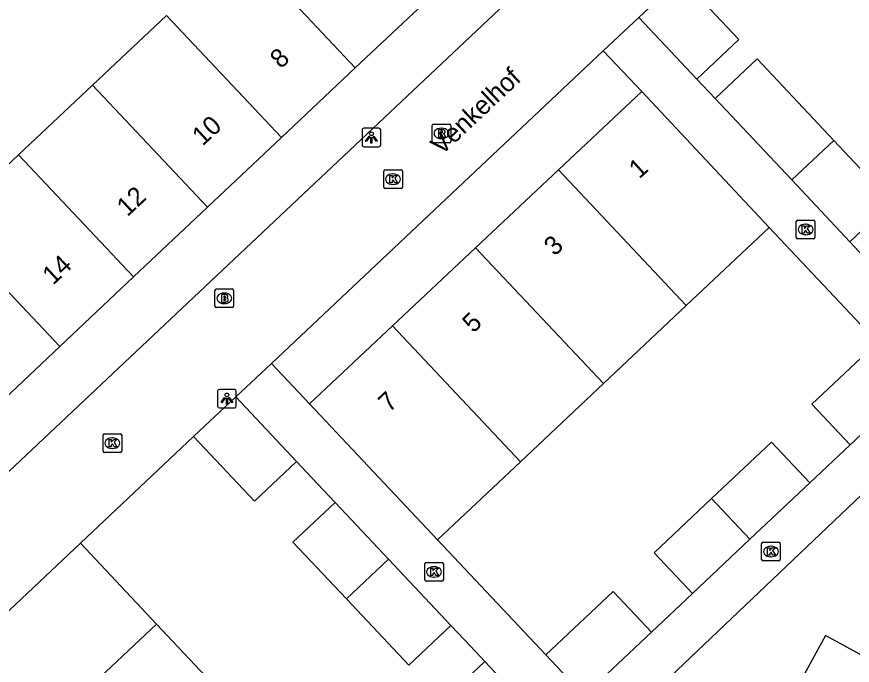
# Model space of a CAD drawing. Extents: x 162542 to 163144, y 380786 to 381511.
# Drawn here: x 162912.05 to 162956.88, y 381257.93 to 381292.72 of the extents above; entities that cross this region are included whole.
import ezdxf

# ---------------------------------------------------------------- set-up
doc = ezdxf.new("R2010")
doc.units = 0
for name, color, linetype in [('IMGEO_Brandkraan', 7, 'Continuous'), ('IMGEO_Kolk', 7, 'Continuous'), ('IMGEO_Lichtpunt', 7, 'Continuous'), ('IMGEO_Muur', 7, 'Continuous'), ('IMGEO_Openbare_ruimte_label', 7, 'Continuous'), ('IMGEO_Pand', 7, 'Continuous'), ('IMGEO_Pand_nummerreeks', 7, 'Continuous'), ('IMGEO_Rijbaan_lokaal_open', 7, 'Continuous'), ('IMGEO_Rioolput', 7, 'Continuous'), ('IMGEO_Voetpad_open', 7, 'Continuous')]:
    doc.layers.add(name, color=color, linetype=linetype)

msp = doc.modelspace()

# ---------------------------------------------------------------- linework, layer by layer
at = {"layer": 'IMGEO_Brandkraan'}
for p, q in [((162922.686, 381277.188), (162922.686, 381278.04)), ((162922.761, 381278.114), (162923.613, 381278.114)), ((162923.174, 381277.894), (162923.199, 381277.894)), ((162923.687, 381278.04), (162923.687, 381277.188)), ((162923.197, 381277.334), (162923.172, 381277.334)), ((162923.613, 381277.114), (162922.761, 381277.114))]:
    msp.add_line(p, q, dxfattribs=at)
for points in [[(162922.686, 381277.188), (162922.686, 381278.04)], [(162922.761, 381278.114), (162923.613, 381278.114)], [(162923.034, 381277.814), (162923.034, 381277.414), (162923.247, 381277.414)], [(162923.265, 381277.814), (162923.034, 381277.814)], [(162923.213, 381277.733), (162923.159, 381277.733), (162923.159, 381277.657)], [(162923.687, 381278.04), (162923.687, 381277.188)], [(162923.159, 381277.657), (162923.212, 381277.657)], [(162923.221, 381277.581), (162923.159, 381277.581), (162923.159, 381277.5)], [(162923.159, 381277.5), (162923.221, 381277.5)], [(162923.613, 381277.114), (162922.761, 381277.114)]]:
    msp.add_lwpolyline(points, dxfattribs=at)
for centre, radius, start, end in [((162922.763, 381278.038), 0.0765, 91.552, 178.448), ((162922.763, 381278.038), 0.0765, 91.552, 178.448), ((162923.214, 381277.695), 0.0379, 267.8285, 90.9355), ((162923.269, 381277.669), 0.145, 59.4692, 91.5367), ((162923.294, 381277.716), 0.0922, 285.5137, 58.1501), ((162923.611, 381278.038), 0.0765, 1.552, 88.448), ((162923.611, 381278.038), 0.0765, 1.552, 88.448), ((162923.222, 381277.54), 0.0404, 269.8759, 90.5077), ((162923.253, 381277.665), 0.251, 268.6676, 293.5347), ((162923.299, 381277.524), 0.105, 301.3115, 78.989), ((162922.763, 381277.19), 0.0765, 181.552, 268.448), ((162922.763, 381277.19), 0.0765, 181.552, 268.448), ((162923.611, 381277.19), 0.0765, 271.552, 358.448), ((162923.611, 381277.19), 0.0765, 271.552, 358.448)]:
    msp.add_arc(centre, radius, start, end, dxfattribs=at)
for centre, major_axis, ratio, start_param, end_param in [((162923.173, 381277.614), (-0.387, 0.002), 0.722429, 4.712389, 7.853982), ((162923.198, 381277.614), (-0.39, 0.002), 0.717154, 1.570796, 4.712389)]:
    msp.add_ellipse(centre, major_axis=major_axis, ratio=ratio, start_param=start_param, end_param=end_param, dxfattribs=at)
at = {"layer": 'IMGEO_Kolk'}
for p, q in [((162931.742, 381283.579), (162931.742, 381284.431)), ((162931.817, 381284.505), (162932.669, 381284.505)), ((162932.743, 381284.431), (162932.743, 381283.579)), ((162932.23, 381284.285), (162932.255, 381284.285)), ((162932.253, 381283.725), (162932.228, 381283.725)), ((162932.669, 381283.505), (162931.817, 381283.505)), ((162953.871, 381280.88), (162953.871, 381281.732)), ((162953.946, 381281.806), (162954.798, 381281.806)), ((162954.872, 381281.732), (162954.872, 381280.88)), ((162954.359, 381281.586), (162954.384, 381281.586)), ((162954.382, 381281.026), (162954.357, 381281.026)), ((162954.798, 381280.806), (162953.946, 381280.806)), ((162916.684, 381269.416), (162916.684, 381270.268)), ((162916.759, 381270.342), (162917.611, 381270.342)), ((162917.172, 381270.122), (162917.197, 381270.122)), ((162917.685, 381270.268), (162917.685, 381269.416)), ((162917.611, 381269.342), (162916.759, 381269.342)), ((162917.195, 381269.562), (162917.17, 381269.562)), ((162952.01, 381263.603), (162952.01, 381264.455)), ((162952.085, 381264.529), (162952.937, 381264.529)), ((162952.498, 381264.309), (162952.523, 381264.309)), ((162953.011, 381264.455), (162953.011, 381263.603)), ((162933.939, 381262.512), (162933.939, 381263.364)), ((162934.014, 381263.438), (162934.866, 381263.438)), ((162934.94, 381263.364), (162934.94, 381262.512)), ((162952.937, 381263.529), (162952.085, 381263.529)), ((162952.521, 381263.749), (162952.496, 381263.749)), ((162934.427, 381263.218), (162934.452, 381263.218)), ((162934.45, 381262.658), (162934.425, 381262.658)), ((162934.866, 381262.438), (162934.014, 381262.438))]:
    msp.add_line(p, q, dxfattribs=at)
for points in [[(162931.742, 381283.579), (162931.742, 381284.431)], [(162931.817, 381284.505), (162932.669, 381284.505)], [(162932.743, 381284.431), (162932.743, 381283.579)], [(162932.063, 381284.205), (162932.186, 381284.205), (162932.186, 381284.054), (162932.316, 381284.205), (162932.48, 381284.205), (162932.334, 381284.054), (162932.487, 381283.805), (162932.335, 381283.805), (162932.25, 381283.969), (162932.186, 381283.902), (162932.186, 381283.805), (162932.063, 381283.805), (162932.063, 381284.205)], [(162932.669, 381283.505), (162931.817, 381283.505)], [(162953.871, 381280.88), (162953.871, 381281.732)], [(162953.946, 381281.806), (162954.798, 381281.806)], [(162954.872, 381281.732), (162954.872, 381280.88)], [(162954.192, 381281.506), (162954.315, 381281.506), (162954.315, 381281.355), (162954.445, 381281.506), (162954.609, 381281.506), (162954.463, 381281.355), (162954.616, 381281.106), (162954.464, 381281.106), (162954.379, 381281.27), (162954.315, 381281.203), (162954.315, 381281.106), (162954.192, 381281.106), (162954.192, 381281.506)], [(162954.798, 381280.806), (162953.946, 381280.806)], [(162916.684, 381269.416), (162916.684, 381270.268)], [(162916.759, 381270.342), (162917.611, 381270.342)], [(162917.685, 381270.268), (162917.685, 381269.416)], [(162917.005, 381270.042), (162917.128, 381270.042), (162917.128, 381269.891), (162917.258, 381270.042), (162917.422, 381270.042), (162917.276, 381269.891), (162917.429, 381269.642), (162917.277, 381269.642), (162917.192, 381269.806), (162917.128, 381269.739), (162917.128, 381269.642), (162917.005, 381269.642), (162917.005, 381270.042)], [(162917.611, 381269.342), (162916.759, 381269.342)], [(162952.01, 381263.603), (162952.01, 381264.455)], [(162952.085, 381264.529), (162952.937, 381264.529)], [(162953.011, 381264.455), (162953.011, 381263.603)], [(162952.331, 381264.229), (162952.454, 381264.229), (162952.454, 381264.078), (162952.584, 381264.229), (162952.748, 381264.229), (162952.602, 381264.078), (162952.755, 381263.829), (162952.603, 381263.829), (162952.518, 381263.993), (162952.454, 381263.926), (162952.454, 381263.829), (162952.331, 381263.829), (162952.331, 381264.229)], [(162933.939, 381262.512), (162933.939, 381263.364)], [(162934.014, 381263.438), (162934.866, 381263.438)], [(162934.94, 381263.364), (162934.94, 381262.512)], [(162952.937, 381263.529), (162952.085, 381263.529)], [(162934.26, 381263.138), (162934.383, 381263.138), (162934.383, 381262.987), (162934.513, 381263.138), (162934.677, 381263.138), (162934.531, 381262.987), (162934.684, 381262.738), (162934.532, 381262.738), (162934.447, 381262.902), (162934.383, 381262.835), (162934.383, 381262.738), (162934.26, 381262.738), (162934.26, 381263.138)], [(162934.866, 381262.438), (162934.014, 381262.438)]]:
    msp.add_lwpolyline(points, dxfattribs=at)
for centre, start, end in [((162931.819, 381284.429), 91.552, 178.448), ((162931.819, 381284.429), 91.552, 178.448), ((162932.667, 381284.429), 1.552, 88.448), ((162932.667, 381284.429), 1.552, 88.448), ((162931.819, 381283.581), 181.552, 268.448), ((162931.819, 381283.581), 181.552, 268.448), ((162932.667, 381283.581), 271.552, 358.448), ((162932.667, 381283.581), 271.552, 358.448), ((162953.948, 381281.73), 91.552, 178.448), ((162953.948, 381281.73), 91.552, 178.448), ((162954.796, 381281.73), 1.552, 88.448), ((162954.796, 381281.73), 1.552, 88.448), ((162953.948, 381280.882), 181.552, 268.448), ((162953.948, 381280.882), 181.552, 268.448), ((162954.796, 381280.882), 271.552, 358.448), ((162954.796, 381280.882), 271.552, 358.448), ((162916.761, 381270.266), 91.552, 178.448), ((162916.761, 381270.266), 91.552, 178.448), ((162917.609, 381270.266), 1.552, 88.448), ((162917.609, 381270.266), 1.552, 88.448), ((162916.761, 381269.418), 181.552, 268.448), ((162916.761, 381269.418), 181.552, 268.448), ((162917.609, 381269.418), 271.552, 358.448), ((162917.609, 381269.418), 271.552, 358.448), ((162952.087, 381264.453), 91.552, 178.448), ((162952.087, 381264.453), 91.552, 178.448), ((162952.935, 381264.453), 1.552, 88.448), ((162952.935, 381264.453), 1.552, 88.448), ((162934.016, 381263.362), 91.552, 178.448), ((162934.016, 381263.362), 91.552, 178.448), ((162934.864, 381263.362), 1.552, 88.448), ((162934.864, 381263.362), 1.552, 88.448), ((162952.087, 381263.605), 181.552, 268.448), ((162952.087, 381263.605), 181.552, 268.448), ((162952.935, 381263.605), 271.552, 358.448), ((162952.935, 381263.605), 271.552, 358.448), ((162934.016, 381262.514), 181.552, 268.448), ((162934.016, 381262.514), 181.552, 268.448), ((162934.864, 381262.514), 271.552, 358.448), ((162934.864, 381262.514), 271.552, 358.448)]:
    msp.add_arc(centre, 0.0765, start, end, dxfattribs=at)
for centre, major_axis, ratio, start_param, end_param in [((162932.229, 381284.005), (-0.387, 0.002), 0.722429, 4.712389, 7.853982), ((162932.254, 381284.005), (-0.39, 0.002), 0.717154, 1.570796, 4.712389), ((162954.358, 381281.306), (-0.387, 0.002), 0.722429, 4.712389, 7.853982), ((162954.383, 381281.306), (-0.39, 0.002), 0.717154, 1.570796, 4.712389), ((162917.171, 381269.842), (-0.387, 0.002), 0.722429, 4.712389, 7.853982), ((162917.196, 381269.842), (-0.39, 0.002), 0.717154, 1.570796, 4.712389), ((162952.497, 381264.029), (-0.387, 0.002), 0.722429, 4.712389, 7.853982), ((162952.522, 381264.029), (-0.39, 0.002), 0.717154, 1.570796, 4.712389), ((162934.426, 381262.938), (-0.387, 0.002), 0.722429, 4.712389, 7.853982), ((162934.451, 381262.938), (-0.39, 0.002), 0.717154, 1.570796, 4.712389)]:
    msp.add_ellipse(centre, major_axis=major_axis, ratio=ratio, start_param=start_param, end_param=end_param, dxfattribs=at)
at = {"layer": 'IMGEO_Lichtpunt'}
for p, q in [((162931.483, 381286.74), (162930.675, 381286.74)), ((162931.483, 381286.74), (162930.675, 381286.74)), ((162930.581, 381286.645), (162930.581, 381285.838)), ((162930.581, 381286.645), (162930.581, 381285.838)), ((162931.577, 381285.838), (162931.577, 381286.645)), ((162931.577, 381285.838), (162931.577, 381286.645)), ((162930.675, 381285.744), (162931.483, 381285.744)), ((162930.675, 381285.744), (162931.483, 381285.744)), ((162922.831, 381272.633), (162922.831, 381271.826)), ((162922.831, 381272.633), (162922.831, 381271.826)), ((162923.733, 381272.728), (162922.925, 381272.728)), ((162923.733, 381272.728), (162922.925, 381272.728)), ((162923.827, 381271.826), (162923.827, 381272.633)), ((162923.827, 381271.826), (162923.827, 381272.633)), ((162922.925, 381271.732), (162923.733, 381271.732)), ((162922.925, 381271.732), (162923.733, 381271.732))]:
    msp.add_line(p, q, dxfattribs=at)
for points in [[(162930.955, 381286.309), (162930.994, 381286.281), (162930.806, 381286.019), (162930.768, 381286.046), (162930.955, 381286.309)], [(162931.057, 381286.261), (162931.104, 381286.261), (162931.104, 381285.939), (162931.057, 381285.939), (162931.057, 381286.261)], [(162931.167, 381286.281), (162931.205, 381286.308), (162931.392, 381286.046), (162931.353, 381286.018), (162931.167, 381286.281)], [(162923.205, 381272.297), (162923.244, 381272.269), (162923.056, 381272.007), (162923.018, 381272.034), (162923.205, 381272.297)], [(162923.307, 381272.249), (162923.354, 381272.249), (162923.354, 381271.927), (162923.307, 381271.927), (162923.307, 381272.249)], [(162923.417, 381272.269), (162923.455, 381272.296), (162923.642, 381272.034), (162923.603, 381272.006), (162923.417, 381272.269)]]:
    msp.add_lwpolyline(points, dxfattribs=at)
for centre in [(162931.08, 381286.443), (162923.33, 381272.431)]:
    msp.add_circle(centre, 0.0994, dxfattribs=at)
for centre, start, end in [((162930.675, 381286.645), 90, 180), ((162930.675, 381286.645), 90, 180), ((162931.483, 381286.645), 0, 90), ((162931.483, 381286.645), 0, 90), ((162930.675, 381285.838), 180, 270), ((162930.675, 381285.838), 180, 270), ((162931.483, 381285.838), 270, 0), ((162931.483, 381285.838), 270, 360), ((162922.925, 381272.633), 90, 180), ((162922.925, 381272.633), 90, 180), ((162923.733, 381272.633), 0, 90), ((162923.733, 381272.633), 0, 90), ((162922.925, 381271.826), 180, 270), ((162922.925, 381271.826), 180, 270), ((162923.733, 381271.826), 270, 0), ((162923.733, 381271.826), 270, 360)]:
    msp.add_arc(centre, 0.0946, start, end, dxfattribs=at)
at = {"layer": 'IMGEO_Muur'}
for points in [[(162902.331, 381259.587), (162950.027, 381304.513)], [(162921.544, 381270.198), (162915.467, 381264.485)]]:
    msp.add_lwpolyline(points, dxfattribs=at)
at = {"layer": 'IMGEO_Pand'}
for points in [[(162930.217, 381289.986), (162924.051, 381296.522)], [(162945.419, 381292.684), (162947.676, 381294.809)], [(162947.676, 381294.809), (162950.796, 381291.492), (162948.538, 381289.368)], [(162930.217, 381289.986), (162934.185, 381293.722)], [(162920.085, 381292.784), (162916.119, 381289.046)], [(162920.085, 381292.784), (162926.256, 381286.242)], [(162948.538, 381289.368), (162945.419, 381292.684)], [(162949.513, 381288.332), (162951.77, 381290.457), (162955.882, 381286.087)], [(162926.256, 381286.242), (162930.217, 381289.986)], [(162916.119, 381289.046), (162912.152, 381285.308)], [(162922.29, 381282.504), (162916.119, 381289.046)], [(162941.12, 381284.513), (162945.579, 381288.705)], [(162945.579, 381288.705), (162952.425, 381281.42)], [(162953.625, 381283.962), (162949.513, 381288.332)], [(162922.29, 381282.504), (162926.256, 381286.242)], [(162955.882, 381286.087), (162953.625, 381283.962)], [(162956.741, 381280.65), (162958.999, 381282.774), (162955.882, 381286.087)], [(162912.152, 381285.308), (162908.186, 381281.57)], [(162918.324, 381278.766), (162912.152, 381285.308)], [(162936.666, 381280.326), (162941.12, 381284.513)], [(162941.12, 381284.513), (162947.973, 381277.229)], [(162953.625, 381283.962), (162956.741, 381280.65)], [(162918.324, 381278.766), (162922.29, 381282.504)], [(162914.358, 381275.029), (162908.186, 381281.57)], [(162947.973, 381277.229), (162952.425, 381281.42)], [(162932.213, 381276.139), (162936.666, 381280.326)], [(162943.522, 381273.039), (162936.666, 381280.326)], [(162914.358, 381275.029), (162918.324, 381278.766)], [(162943.522, 381273.039), (162947.973, 381277.229)], [(162927.759, 381271.951), (162932.213, 381276.139)], [(162932.213, 381276.139), (162939.071, 381268.849)], [(162910.392, 381271.291), (162914.358, 381275.029)], [(162958.221, 381275.251), (162954.699, 381271.934), (162956.755, 381269.75)], [(162956.755, 381269.75), (162960.278, 381273.068), (162958.221, 381275.251)], [(162939.071, 381268.849), (162943.522, 381273.039)], [(162921.544, 381270.198), (162923.803, 381272.321)], [(162923.803, 381272.321), (162927.062, 381268.86)], [(162934.62, 381264.658), (162927.759, 381271.951)], [(162921.544, 381270.198), (162924.807, 381266.733), (162927.062, 381268.86)], [(162954.596, 381267.716), (162952.54, 381269.9), (162949.325, 381266.871)], [(162934.62, 381264.658), (162939.071, 381268.849)], [(162954.596, 381267.716), (162951.38, 381264.687)], [(162929.127, 381266.666), (162926.872, 381264.54), (162929.74, 381261.494)], [(162929.127, 381266.666), (162931.995, 381263.621)], [(162948.298, 381261.783), (162946.242, 381263.968), (162949.325, 381266.871)], [(162949.325, 381266.871), (162951.38, 381264.687)], [(162908.191, 381257.623), (162915.467, 381264.485)], [(162919.558, 381260.139), (162915.467, 381264.485)], [(162951.38, 381264.687), (162948.298, 381261.783)], [(162929.74, 381261.494), (162931.995, 381263.621)], [(162931.995, 381263.621), (162935.344, 381260.065)], [(162946.098, 381259.71), (162944.041, 381261.894), (162940.432, 381258.495)], [(162929.74, 381261.494), (162933.091, 381257.935), (162935.344, 381260.065)], [(162919.558, 381260.139), (162912.283, 381253.278)], [(162923.671, 381255.771), (162919.558, 381260.139)], [(162946.098, 381259.71), (162942.489, 381256.312), (162940.432, 381258.495)], [(162937.17, 381258.126), (162934.914, 381255.999), (162937.967, 381252.758)], [(162937.17, 381258.126), (162940.222, 381254.884)]]:
    msp.add_lwpolyline(points, dxfattribs=at)
at = {"layer": 'IMGEO_Rijbaan_lokaal_open'}
for points in [[(162959.44, 381313.384), (162950.027, 381304.513), (162902.331, 381259.587)], [(162945.419, 381292.684), (162943.518, 381290.893)], [(162943.518, 381290.893), (162925.714, 381274.122)], [(162925.714, 381274.122), (162923.803, 381272.321)], [(162915.467, 381264.485), (162921.544, 381270.198)]]:
    msp.add_lwpolyline(points, dxfattribs=at)
at = {"layer": 'IMGEO_Rioolput'}
for p, q in [((162934.338, 381286.034), (162934.338, 381286.886)), ((162934.413, 381286.96), (162935.265, 381286.96)), ((162934.826, 381286.74), (162934.851, 381286.74)), ((162935.339, 381286.886), (162935.339, 381286.034)), ((162935.265, 381285.96), (162934.413, 381285.96)), ((162934.849, 381286.18), (162934.824, 381286.18))]:
    msp.add_line(p, q, dxfattribs=at)
for points in [[(162934.338, 381286.034), (162934.338, 381286.886)], [(162934.413, 381286.96), (162935.265, 381286.96)], [(162934.927, 381286.658), (162934.675, 381286.66), (162934.675, 381286.26)], [(162935.339, 381286.886), (162935.339, 381286.034)], [(162934.675, 381286.26), (162934.799, 381286.26), (162934.799, 381286.422), (162934.81, 381286.422)], [(162934.853, 381286.579), (162934.799, 381286.579), (162934.799, 381286.498)], [(162934.799, 381286.498), (162934.851, 381286.498)], [(162934.857, 381286.393), (162934.928, 381286.26), (162935.068, 381286.26), (162935.003, 381286.386)], [(162935.265, 381285.96), (162934.413, 381285.96)]]:
    msp.add_lwpolyline(points, dxfattribs=at)
for centre, radius, start, end in [((162934.415, 381286.884), 0.0765, 91.552, 178.448), ((162934.415, 381286.884), 0.0765, 91.552, 178.448), ((162934.926, 381286.548), 0.109, 350.3612, 89.416), ((162935.263, 381286.884), 0.0765, 1.552, 88.448), ((162935.263, 381286.884), 0.0765, 1.552, 88.448), ((162934.809, 381286.369), 0.0533, 26.0293, 88.6989), ((162934.835, 381286.687), 0.19, 274.7715, 282.9687), ((162934.859, 381286.483), 0.0964, 77.0061, 93.1865), ((162934.873, 381286.54), 0.0378, 276.6634, 79.6772), ((162934.924, 381286.548), 0.112, 277.5842, 350.9817), ((162934.908, 381286.333), 0.108, 29.5134, 73.7905), ((162934.415, 381286.036), 0.0765, 181.552, 268.448), ((162934.415, 381286.036), 0.0765, 181.552, 268.448), ((162935.263, 381286.036), 0.0765, 271.552, 358.448), ((162935.263, 381286.036), 0.0765, 271.552, 358.448)]:
    msp.add_arc(centre, radius, start, end, dxfattribs=at)
for centre, major_axis, ratio, start_param, end_param in [((162934.825, 381286.46), (-0.387, 0.002), 0.722429, 4.712389, 7.853982), ((162934.85, 381286.46), (-0.39, 0.002), 0.717154, 1.570796, 4.712389)]:
    msp.add_ellipse(centre, major_axis=major_axis, ratio=ratio, start_param=start_param, end_param=end_param, dxfattribs=at)
at = {"layer": 'IMGEO_Voetpad_open'}
for points in [[(162943.518, 381290.893), (162945.579, 381288.705)], [(162949.513, 381288.332), (162948.538, 381289.368)], [(162952.425, 381281.42), (162958.221, 381275.251)], [(162958.985, 381278.265), (162957.736, 381279.592), (162956.741, 381280.65)], [(162927.759, 381271.951), (162925.714, 381274.122)], [(162950.849, 381251.129), (162944.181, 381254.516), (162961.75, 381271.244), (162970.642, 381259.25), (162967.083, 381253.164), (162955.438, 381259.527), (162950.849, 381251.129)], [(162956.755, 381269.75), (162954.596, 381267.716)], [(162927.062, 381268.86), (162927.882, 381267.989), (162929.127, 381266.666)], [(162940.432, 381258.495), (162934.62, 381264.658)], [(162948.298, 381261.783), (162946.098, 381259.71)], [(162935.344, 381260.065), (162936.109, 381259.253), (162937.17, 381258.126)]]:
    msp.add_lwpolyline(points, dxfattribs=at)

# ---------------------------------------------------------------- texts
at = {"layer": 'IMGEO_Openbare_ruimte_label'}
msp.add_text('Venkelhof', height=1, rotation=43.2986, dxfattribs=at).set_placement((162934.843, 381285.25))
at = {"layer": 'IMGEO_Pand_nummerreeks'}
for s, rotation, p in [('8', 43.0251, (162926.217, 381289.892)), ('10', 42.5998, (162922.029, 381285.756)), ('1', 41.9552, (162945.448, 381283.992)), ('12', 43.0021, (162917.993, 381281.963)), ('3', 42.6264, (162940.903, 381279.844)), ('14', 42.9786, (162914.001, 381278.287)), ('5', 44.2559, (162936.55, 381275.713)), ('7', 43.7746, (162932.035, 381271.462))]:
    msp.add_text(s, height=1, rotation=rotation, dxfattribs=at).set_placement(p)

doc.saveas('drawing.dxf')
